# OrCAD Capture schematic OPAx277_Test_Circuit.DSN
size A; title: OPAx277 High Precision Operational Amplifiers; rev: 1.4; note: Datasheet: SBOS079B  EVM: N/A
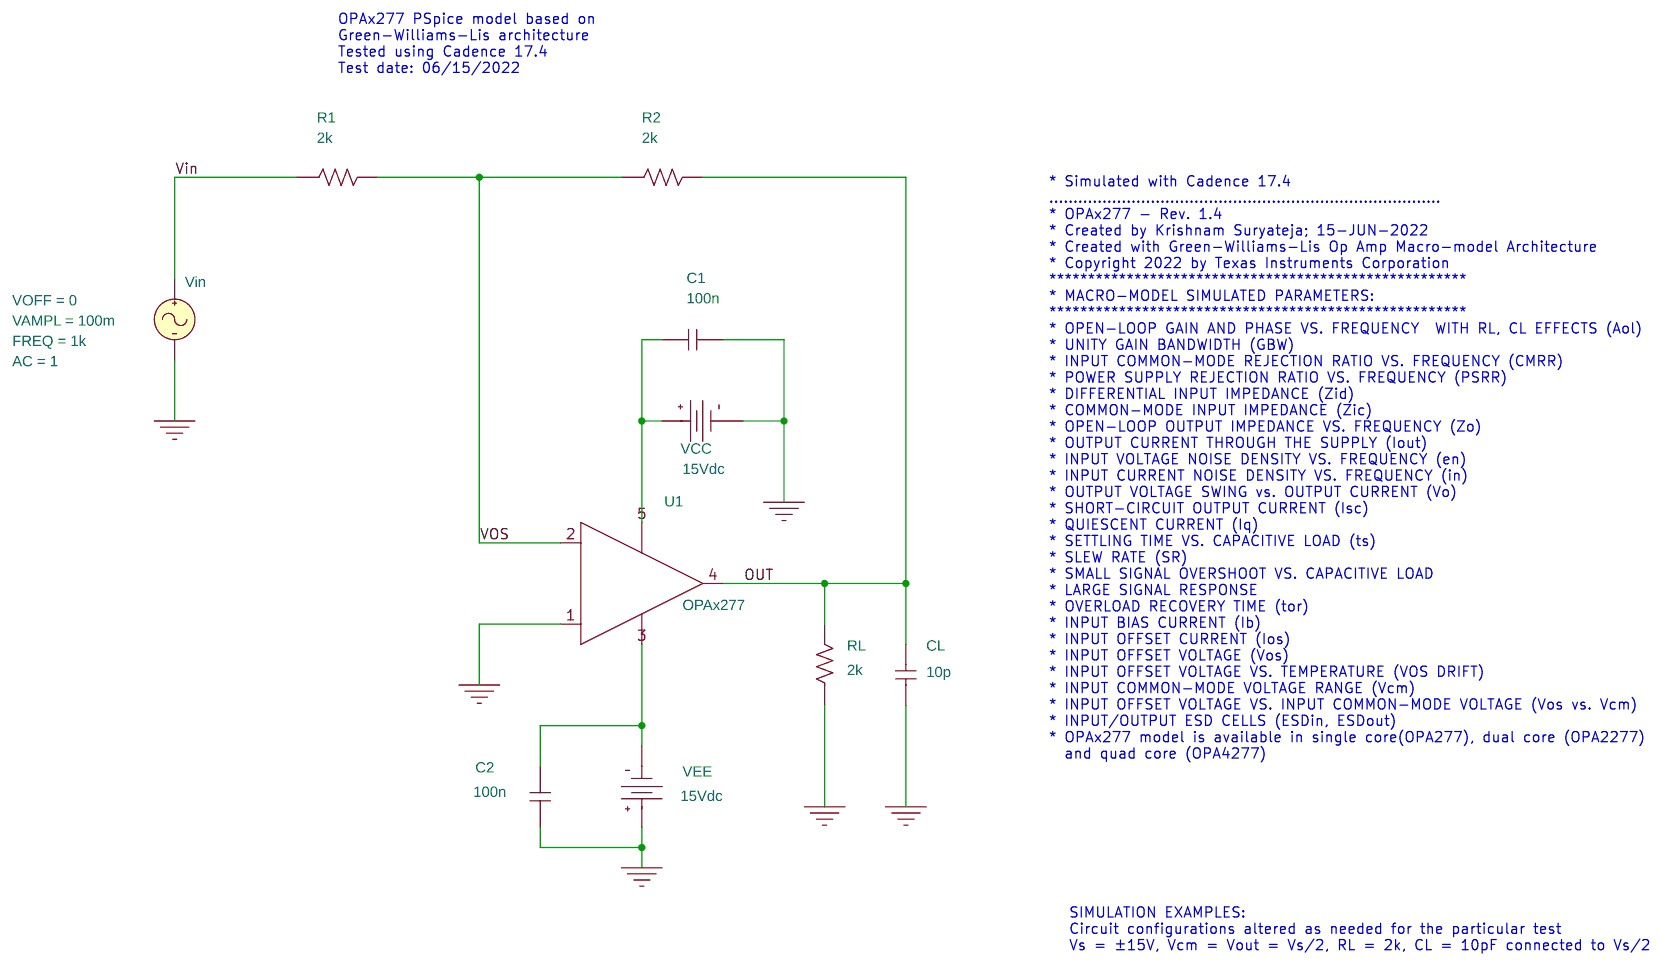
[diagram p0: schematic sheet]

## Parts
C1  100n  [cap196]
C2  100n  [cap196]
CL  10p  [cap196]
R1  2k  [AXRC05]
R2  2k  [AXRC05]
RL  2k  [AXRC05]
U1  OPAx277
VCC  VDC
VEE  VDC
Vin  VSIN

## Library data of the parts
C1 C2 CL = C
R1 R2 RL = R
U1 = OPAx277
VCC VEE = VDC: DC: 15Vdc
Vin = VSIN: AC: 1; FREQ: 1k; VAMPL: 100m; VOFF: 0

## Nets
Vin: R1.1 Vin.1(+)
0: C1.2 C2.1 CL.2 RL.1 U1.1(+) VCC.1(-) VEE.0(+) Vin.2(-)
OUT: CL.1 R2.2 RL.2 U1.4(OUT)
VOS: R1.2 R2.1 U1.2(-)
N27303: C1.1 U1.5(V+) VCC.0(+)
N27354: C2.2 U1.3(V-) VEE.1(-)

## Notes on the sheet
- OPAx277 PSpice model based on
  Green-Williams-Lis architecture
  Tested using Cadence 17.4
  Test date: 06/15/2022
- * Simulated with Cadence 17.4
  .................................................................................
  * OPAx277 - Rev. 1.4
  * Created by Krishnam Suryateja; 15-JUN-2022
  * Created with Green-Williams-Lis Op Amp Macro-model Architecture
  * Copyright 2022 by Texas Instruments Corporation
  ******************************************************
  * MACRO-MODEL SIMULATED PARAMETERS:
  ******************************************************
  * OPEN-LOOP GAIN AND PHASE VS. FREQUENCY  WITH RL, CL EFFECTS (Aol)
  * UNITY GAIN BANDWIDTH (GBW)
  * INPUT COMMON-MODE REJECTION RATIO VS. FREQUENCY (CMRR)
  * POWER SUPPLY REJECTION RATIO VS. FREQUENCY (PSRR)
  * DIFFERENTIAL INPUT IMPEDANCE (Zid)
  * COMMON-MODE INPUT IMPEDANCE (Zic)
  * OPEN-LOOP OUTPUT IMPEDANCE VS. FREQUENCY (Zo)
  * OUTPUT CURRENT THROUGH THE SUPPLY (Iout)
  * INPUT VOLTAGE NOISE DENSITY VS. FREQUENCY (en)
  * INPUT CURRENT NOISE DENSITY VS. FREQUENCY (in)
  * OUTPUT VOLTAGE SWING vs. OUTPUT CURRENT (Vo)
  * SHORT-CIRCUIT OUTPUT CURRENT (Isc)
  * QUIESCENT CURRENT (Iq)
  * SETTLING TIME VS. CAPACITIVE LOAD (ts)
  * SLEW RATE (SR)
  * SMALL SIGNAL OVERSHOOT VS. CAPACITIVE LOAD
  * LARGE SIGNAL RESPONSE
  * OVERLOAD RECOVERY TIME (tor)
  * INPUT BIAS CURRENT (Ib)
  * INPUT OFFSET CURRENT (Ios)
  * INPUT OFFSET VOLTAGE (Vos)
  * INPUT OFFSET VOLTAGE VS. TEMPERATURE (VOS DRIFT)
  * INPUT COMMON-MODE VOLTAGE RANGE (Vcm)
  * INPUT OFFSET VOLTAGE VS. INPUT COMMON-MODE VOLTAGE (Vos vs. Vcm)
  * INPUT/OUTPUT ESD CELLS (ESDin, ESDout)
  * OPAx277 model is available in single core(OPA277), dual core (OPA2277)
    and quad core (OPA4277)
- SIMULATION EXAMPLES:
  Circuit configurations altered as needed for the particular test
  Vs = ±15V, Vcm = Vout = Vs/2, RL = 2k, CL = 10pF connected to Vs/2
